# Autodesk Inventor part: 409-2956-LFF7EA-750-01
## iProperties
Created: 2010-06
Part Number: 409-2956-LFF7EA-750-01
Material: Sch40 CS PIPE SEAMLESS
Description: PIPE
Document SubType Name: Modeling
Designer: S. Boerckel
Engineer: Steve Boerckel
Mass: 2488.07 g
Surface Area: 1634.44 cm^2
Volume: 316.951 cm^3
Density: 7.85 g/cm^3
Cost Center: 2"
SMR: =<COST CENTER> - <Material>
Length: 18.000 in
Title: 2"
Author: S. Boerckel
Revision Number: B
Subject: DEMIN WATER FORWARDING PUMP SKID-7EA
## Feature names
1. Extrusion1
